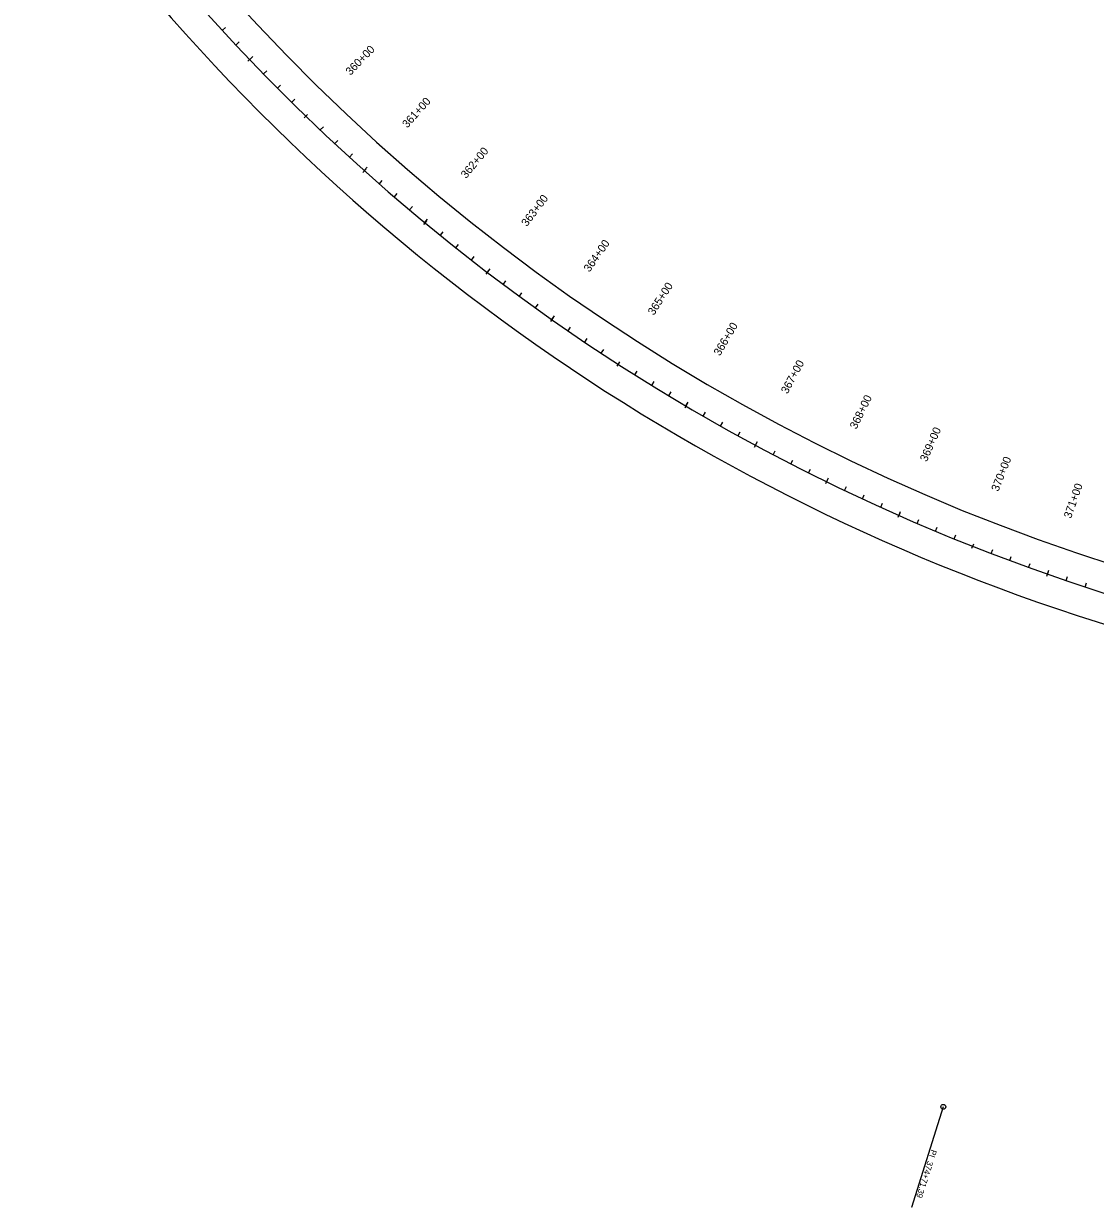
# Model space of a CAD drawing. Extents: x 21369364 to 21378321, y 8396964 to 8399934.
# Drawn here: x 21370256 to 21371598, y 8396964 to 8398446 of the extents above; entities that cross this region are included whole.
import ezdxf

# ---------------------------------------------------------------- set-up
doc = ezdxf.new("R2010")
doc.units = 0
for name, color, linetype in [('Alignment', 7, 'Continuous'), ('Level 1', 7, 'Continuous'), ('Level 60', 7, 'Continuous'), ('TextNonPlot', 7, 'Continuous')]:
    doc.layers.add(name, color=color, linetype=linetype)

msp = doc.modelspace()

# ---------------------------------------------------------------- linework, layer by layer
at = {"layer": 'Alignment'}
msp.add_arc((21372381.2, 8400159.4), 2546.5, 214.6562, 290.16, dxfattribs=at)
at = {"layer": 'Level 1'}
for p in [(21371407.8, 8397089.3), (21371367.9, 8396963.5)]:
    msp.add_line(p, (21371367.9, 8396963.5), dxfattribs=at)
msp.add_circle((21371407.8, 8397089.3), 3.12, dxfattribs=at)
at = {"layer": 'Level 60'}
for p, q in [((21370505, 8398437.7), (21370509, 8398441.4)), ((21370521.9, 8398419.3), (21370525.9, 8398423.1)), ((21370541.3, 8398403.3), (21370536.9, 8398399)), ((21370556.5, 8398383.2), (21370560.4, 8398387)), ((21370574, 8398365.3), (21370577.9, 8398369.2)), ((21370591.7, 8398347.7), (21370595.5, 8398351.6)), ((21370611.7, 8398332.4), (21370607.4, 8398328)), ((21370627.6, 8398312.9), (21370631.4, 8398316.8)), ((21370645.8, 8398295.8), (21370649.5, 8398299.8)), ((21370664.2, 8398278.8), (21370667.9, 8398282.8)), ((21370684.8, 8398264.3), (21370680.7, 8398259.8)), ((21370701.5, 8398245.5), (21370705.1, 8398249.6)), ((21370720.3, 8398229.1), (21370723.9, 8398233.2)), ((21370739.4, 8398212.9), (21370742.9, 8398217)), ((21370760.5, 8398199.2), (21370756.6, 8398194.5)), ((21370777.9, 8398181), (21370781.3, 8398185.2)), ((21370797.4, 8398165.4), (21370800.8, 8398169.6)), ((21370817, 8398149.9), (21370820.4, 8398154.2)), ((21370838.7, 8398137.1), (21370835, 8398132.2)), ((21370856.8, 8398119.6), (21370860.1, 8398124)), ((21370876.9, 8398104.7), (21370880.1, 8398109.1)), ((21370897.1, 8398090), (21370900.3, 8398094.5)), ((21370919.3, 8398078.1), (21370915.8, 8398073.1)), ((21370938.1, 8398061.3), (21370941.1, 8398065.8)), ((21370958.7, 8398047.2), (21370961.8, 8398051.8)), ((21370979.5, 8398033.4), (21370982.5, 8398037.9)), ((21371002.1, 8398022.3), (21370998.8, 8398017.1)), ((21371021.5, 8398006.3), (21371024.5, 8398010.9)), ((21371042.7, 8397993), (21371045.6, 8397997.7)), ((21371064.1, 8397980), (21371066.9, 8397984.7)), ((21371087.1, 8397969.8), (21371084, 8397964.5)), ((21371107.1, 8397954.5), (21371109.8, 8397959.3)), ((21371128.8, 8397942.1), (21371131.5, 8397946.9)), ((21371150.7, 8397930), (21371153.3, 8397934.7)), ((21371174, 8397920.7), (21371171.1, 8397915.3)), ((21371194.7, 8397906.2), (21371197.2, 8397911.1)), ((21371216.8, 8397894.7), (21371219.3, 8397899.5)), ((21371239.1, 8397883.4), (21371241.6, 8397888.2)), ((21371262.9, 8397875), (21371260.2, 8397869.5)), ((21371284, 8397861.4), (21371286.4, 8397866.3)), ((21371306.6, 8397850.7), (21371308.9, 8397855.7)), ((21371329.4, 8397840.3), (21371331.6, 8397845.3)), ((21371353.4, 8397832.9), (21371350.9, 8397827.3)), ((21371375.1, 8397820.1), (21371377.3, 8397825.1)), ((21371398.1, 8397810.3), (21371400.2, 8397815.3)), ((21371421.2, 8397800.8), (21371423.3, 8397805.8)), ((21371445.5, 8397794.3), (21371443.3, 8397788.6)), ((21371467.7, 8397782.4), (21371469.7, 8397787.5)), ((21371491.1, 8397773.5), (21371493, 8397778.6)), ((21371514.6, 8397764.9), (21371516.4, 8397770)), ((21371539.1, 8397759.4), (21371537.1, 8397753.6)), ((21371561.7, 8397748.4), (21371563.5, 8397753.5)), ((21371585.4, 8397740.4), (21371587.2, 8397745.6))]:
    msp.add_line(p, q, dxfattribs=at)
at = {"layer": 'TextNonPlot'}
for p, q in [((21370539.1, 8398401.2), (21370543.1, 8398404.9)), ((21370611.7, 8398332.4), (21370607.4, 8398328)), ((21370682.7, 8398262.1), (21370686.4, 8398266.1)), ((21370758.5, 8398196.8), (21370762, 8398201)), ((21370836.8, 8398134.6), (21370840.2, 8398139)), ((21370917.5, 8398075.6), (21370920.7, 8398080)), ((21371002.1, 8398022.3), (21370998.8, 8398017.1)), ((21371085.5, 8397967.2), (21371088.3, 8397971.9)), ((21371172.6, 8397918), (21371175.2, 8397922.8)), ((21371261.5, 8397872.3), (21371263.9, 8397877.2)), ((21371352.2, 8397830.1), (21371354.4, 8397835.1)), ((21371445.5, 8397794.3), (21371443.3, 8397788.6)), ((21371538.1, 8397756.5), (21371539.9, 8397761.7))]:
    msp.add_line(p, q, dxfattribs=at)
for radius in [2509.5, 2583.5]:
    msp.add_arc((21372381.2, 8400159.4), radius, 214.6562, 290.16, dxfattribs=at)

# ---------------------------------------------------------------- texts
at = {"layer": 'Level 1'}
for s, p in [('PI ', (21371392.7, 8397036.4)), ('374+71.39', (21371388.2, 8397022.1))]:
    msp.add_text(s, height=7.5, rotation=252.4081, dxfattribs=at).set_placement(p)
at = {"layer": 'Level 60'}
for s, rotation, p in [('360+00', 45.916, (21370665.3, 8398380.6)), ('361+00', 48.166, (21370736.5, 8398314.6)), ('362+00', 50.416, (21370810.2, 8398251.4)), ('363+00', 52.666, (21370886.3, 8398191.2)), ('364+00', 54.916, (21370964.7, 8398134.1)), ('365+00', 57.166, (21371045.3, 8398080)), ('366+00', 59.416, (21371128, 8398029.2)), ('367+00', 61.666, (21371212.6, 8397981.6)), ('368+00', 63.916, (21371299, 8397937.4)), ('369+00', 66.166, (21371387.1, 8397896.6)), ('370+00', 68.416, (21371476.7, 8397859.4)), ('371+00', 70.666, (21371567.7, 8397825.6))]:
    msp.add_text(s, height=10.02, rotation=rotation, dxfattribs=at).set_placement(p)
at = {"layer": 'TextNonPlot'}
for s, rotation, p in [('360+00', 45.916, (21370665.3, 8398380.6)), ('365+00', 57.166, (21371045.3, 8398080)), ('370+00', 68.416, (21371476.7, 8397859.4))]:
    msp.add_text(s, height=10.02, rotation=rotation, dxfattribs=at).set_placement(p)

doc.saveas('drawing.dxf')
